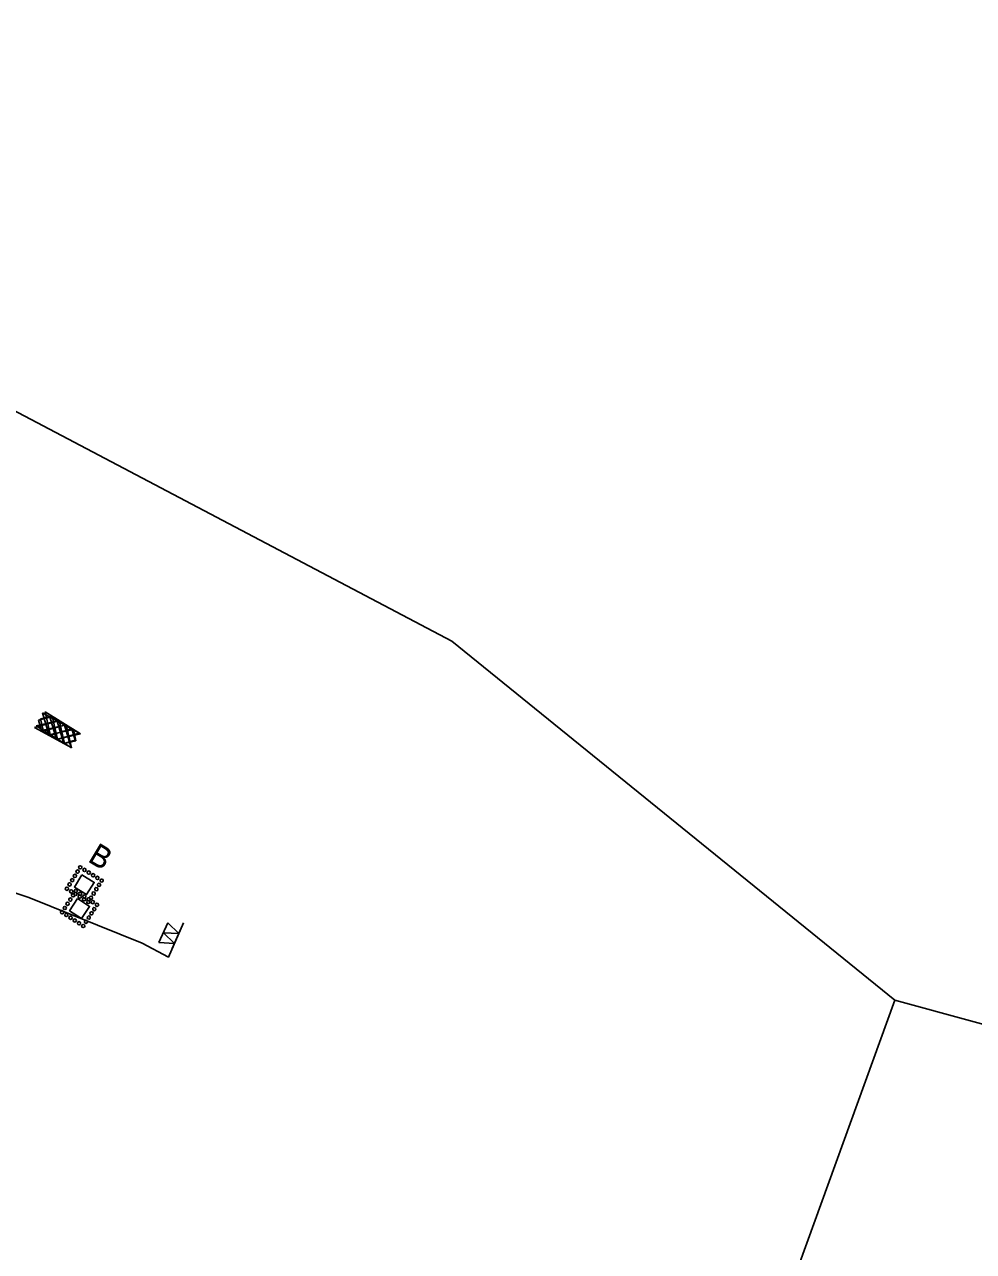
# Model space of a CAD drawing. Extents: x 2283629 to 2286552, y 529718 to 531440.
# Drawn here: x 2284634 to 2285292, y 530589 to 531440 of the extents above; entities that cross this region are included whole.
import ezdxf

# ---------------------------------------------------------------- set-up
doc = ezdxf.new("R2010")
doc.units = 0
for name, color, linetype in [('_CIVIL_CONSTRUCTION', 7, 'Continuous'), ('Draft_Corridor_Graphics_Design', 7, 'Continuous'), ('Draft_RDY_Construction_Class_Element', 7, 'Continuous'), ('P_NCDOT_Terrain_Points_Low', 7, 'Continuous'), ('P_NCDOT_Terrain_Points_Random', 7, 'Continuous'), ('P_NCDOT_Terrain_Void', 7, 'Continuous'), ('P_RDY_Slope_Stake_Fill_Limits', 7, 'Continuous'), ('P_RDY_TC_Pvmt_Asphalt_Intermediate_Course', 7, 'Continuous'), ('P_RDY_TL_Sidewalk', 7, 'Continuous')]:
    doc.layers.add(name, color=color, linetype=linetype)

msp = doc.modelspace()

# ---------------------------------------------------------------- linework, layer by layer
at = {"layer": '_CIVIL_CONSTRUCTION'}
for points in [[(2284118.64, 531439.85), (2283629.48, 530625.47), (2284052.7, 530374.01), (2284693.86, 529987.87), (2284931.04, 529916.94), (2285004.15, 530031.44), (2284997.45, 530131.22), (2285008.79, 530131.98), (2285237.08, 530763.31), (2284930.09, 531012.33)], [(2285237.08, 530763.31), (2285008.79, 530131.98), (2284997.45, 530131.22), (2285004.15, 530031.44), (2284931.04, 529916.94), (2285450.52, 529775.12), (2285986.02, 529718.37), (2286551.75, 529746.45), (2286474.29, 530641.29), (2286008.64, 530618.08), (2285617, 530659.59)]]:
    msp.add_lwpolyline(points, close=True, dxfattribs=at)
at = {"layer": 'P_NCDOT_Terrain_Points_Low'}
for p, q in [((2284733.23, 530816.89), (2284727.17, 530803.17)), ((2284740.86, 530809.42), (2284730.2, 530810.03)), ((2284730.2, 530810.03), (2284737.83, 530802.56)), ((2284733.23, 530816.89), (2284740.86, 530809.42)), ((2284742.38, 530812.85), (2284736.32, 530799.13)), ((2284737.83, 530802.56), (2284727.17, 530803.17))]:
    msp.add_line(p, q, dxfattribs=at)
at = {"layer": 'P_NCDOT_Terrain_Points_Random'}
msp.add_lwpolyline([(2284603.92, 530849.87), (2284606.71, 530844.47), (2284636.9, 530834.54), (2284715.51, 530802.89), (2284733.68, 530793.16), (2284744.13, 530816.82)], dxfattribs=at)
at = {"layer": 'P_NCDOT_Terrain_Void'}
for p, q in [((2284648.19, 530963.34), (2284651.85, 530947.42)), ((2284672.68, 530948.01), (2284648.19, 530963.34)), ((2284642.06, 530953.55), (2284657.98, 530957.21)), ((2284645.1, 530958.43), (2284653.1, 530960.27)), ((2284645.1, 530958.43), (2284646.97, 530950.46)), ((2284653.1, 530960.27), (2284656.77, 530944.35)), ((2284657.98, 530957.21), (2284661.68, 530941.27)), ((2284666.56, 530938.22), (2284642.06, 530953.55)), ((2284646.97, 530950.46), (2284662.89, 530954.14)), ((2284651.85, 530947.42), (2284667.81, 530951.06)), ((2284656.77, 530944.35), (2284672.68, 530948.01)), ((2284662.89, 530954.14), (2284666.56, 530938.22)), ((2284667.81, 530951.06), (2284669.62, 530943.09)), ((2284661.75, 530941.29), (2284669.62, 530943.09))]:
    msp.add_line(p, q, dxfattribs=at)
at = {"layer": 'P_RDY_Slope_Stake_Fill_Limits'}
for p, q in [((2284688.37, 530845.57), (2284688.43, 530845.66)), ((2284682.85, 530836.66), (2284682.89, 530836.72)), ((2284684.69, 530839.63), (2284684.73, 530839.7)), ((2284686.53, 530842.6), (2284686.58, 530842.68))]:
    msp.add_line(p, q, dxfattribs=at)
msp.add_lwpolyline([(2284673.78, 530850.24), (2284682.28, 530844.97), (2284677.01, 530836.47), (2284668.52, 530841.75)], close=True, dxfattribs=at)
for centre in [(2284670.73, 530852.45), (2284672.57, 530855.42), (2284675.54, 530853.58), (2284678.52, 530851.74), (2284665.19, 530843.52), (2284667.04, 530846.5), (2284668.88, 530849.47), (2284681.49, 530849.89), (2284684.47, 530848.05), (2284663.35, 530840.55), (2284666.33, 530838.7), (2284669.3, 530836.86), (2284672.27, 530835.02), (2284680.07, 530834.3), (2284675.25, 530833.17), (2284678.22, 530831.33)]:
    msp.add_circle(centre, 1.12, dxfattribs=at)
for centre, start, end in [((2284685.6, 530843.23), 330.72389, 325.701), ((2284687.44, 530846.2), 331.02038, 325.40452), ((2284681.91, 530837.28), 329.98824, 326.43666), ((2284683.76, 530840.25), 330.38738, 326.03752)]:
    msp.add_arc(centre, 1.12, start, end, dxfattribs=at)
at = {"layer": 'P_RDY_TC_Pvmt_Asphalt_Intermediate_Course'}
for p, q in [((2284685.13, 530828.7), (2284685.19, 530828.79)), ((2284679.41, 530819.92), (2284679.45, 530819.98)), ((2284681.32, 530822.85), (2284681.36, 530822.92)), ((2284683.22, 530825.77), (2284683.28, 530825.86))]:
    msp.add_line(p, q, dxfattribs=at)
msp.add_lwpolyline([(2284670.65, 530833.7), (2284679.03, 530828.24), (2284673.57, 530819.86), (2284665.2, 530825.33)], close=True, dxfattribs=at)
for centre in [(2284667.64, 530835.98), (2284669.55, 530838.91), (2284672.49, 530837), (2284675.42, 530835.09), (2284661.92, 530827.18), (2284663.82, 530830.11), (2284665.73, 530833.04), (2284678.35, 530833.18), (2284681.29, 530831.27), (2284660.01, 530824.24), (2284662.94, 530822.33), (2284665.87, 530820.42), (2284668.8, 530818.51), (2284676.58, 530817.63), (2284671.74, 530816.6), (2284674.67, 530814.69)]:
    msp.add_circle(centre, 1.12, dxfattribs=at)
for centre, start, end in [((2284682.31, 530826.43), 329.4486, 324.42572), ((2284684.22, 530829.36), 329.74509, 324.12923), ((2284678.49, 530820.56), 328.71295, 325.16137), ((2284680.4, 530823.49), 329.11209, 324.76223)]:
    msp.add_arc(centre, 1.12, start, end, dxfattribs=at)
at = {"layer": 'P_RDY_TL_Sidewalk'}
for p, q in [((2284656.65, 530956.86), (2284640.97, 530952.29)), ((2284651.5, 530959.63), (2284643.75, 530957.38)), ((2284646.01, 530949.53), (2284643.75, 530957.38)), ((2284646.53, 530962.42), (2284671.86, 530948.52)), ((2284651.09, 530946.74), (2284646.53, 530962.42)), ((2284656.18, 530943.95), (2284651.57, 530959.65)), ((2284661.22, 530941.18), (2284656.65, 530956.86)), ((2284640.97, 530952.29), (2284666.3, 530938.39)), ((2284661.74, 530954.07), (2284646.01, 530949.53)), ((2284666.78, 530951.32), (2284651.09, 530946.74)), ((2284671.86, 530948.52), (2284656.18, 530943.95)), ((2284666.3, 530938.39), (2284661.74, 530954.07)), ((2284669.11, 530943.47), (2284666.78, 530951.32)), ((2284669.11, 530943.47), (2284661.22, 530941.18))]:
    msp.add_line(p, q, dxfattribs=at)

# ---------------------------------------------------------------- texts
at = {"layer": 'Draft_Corridor_Graphics_Design'}
msp.add_text('B', height=15, rotation=329.00879, dxfattribs=at).set_placement((2284677.38, 530860.03))
at = {"layer": 'Draft_RDY_Construction_Class_Element'}
msp.add_text('B', height=15, rotation=329.00879, dxfattribs=at).set_placement((2284677.16, 530859.8))

doc.saveas('drawing.dxf')
